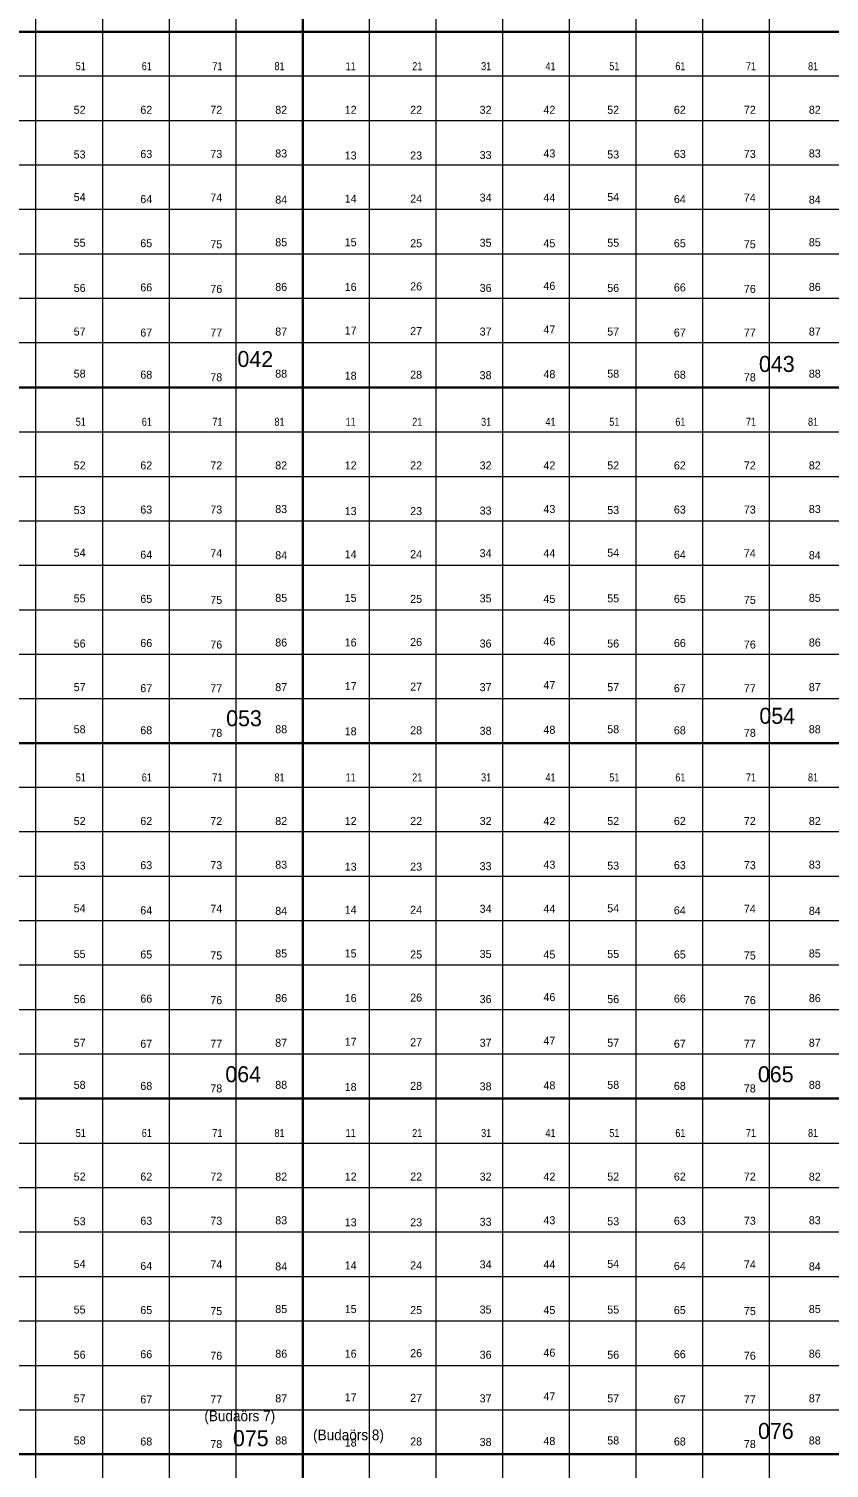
# Model space of a CAD drawing. Extents: x 639000 to 672000, y 222000 to 252000.
# Drawn here: x 643460 to 647960, y 233921 to 242017 of the extents above; entities that cross this region are included whole.
import ezdxf
from ezdxf.enums import TextEntityAlignment as Align

# ---------------------------------------------------------------- set-up
doc = ezdxf.new("R2010")
doc.units = 0
doc.header["$LTSCALE"] = 18
doc.layers.add('1', color=7, linetype='Continuous', lineweight=13)
doc.layers.add('2', color=7, linetype='Continuous')
doc.layers.add('29', color=7, linetype='Continuous')

msp = doc.modelspace()

# ---------------------------------------------------------------- linework, layer by layer
at = {"layer": '1', "lineweight": 35}
for p, q in [((645000, 224000), (645000, 250000)), ((639000, 242000), (672000, 242000)), ((672000, 240000), (639000, 240000)), ((639000, 238000), (672000, 238000)), ((672000, 236000), (639000, 236000)), ((639000, 234000), (672000, 234000))]:
    msp.add_line(p, q, dxfattribs=at)
at = {"layer": '1'}
for p, q in [((645375, 224000), (645375, 250000)), ((645750, 224000), (645750, 250000)), ((646125, 224000), (646125, 250000)), ((646500, 224000), (646500, 250000)), ((646875, 224000), (646875, 250000)), ((647250, 224000), (647250, 250000)), ((647625, 224000), (647625, 250000)), ((643500, 224000), (643500, 248000)), ((643875, 224000), (643875, 248000)), ((644250, 224000), (644250, 248000)), ((644625, 224000), (644625, 248000)), ((672000, 241750), (639000, 241750)), ((672000, 241500), (639000, 241500)), ((672000, 241250), (639000, 241250)), ((672000, 241000), (639000, 241000)), ((672000, 240750), (639000, 240750)), ((672000, 240500), (639000, 240500)), ((672000, 240250), (639000, 240250)), ((639000, 239750), (672000, 239750)), ((639000, 239500), (672000, 239500)), ((639000, 239250), (672000, 239250)), ((639000, 239000), (672000, 239000)), ((639000, 238750), (672000, 238750)), ((639000, 238500), (672000, 238500)), ((639000, 238250), (672000, 238250)), ((672000, 237750), (639000, 237750)), ((672000, 237500), (639000, 237500)), ((672000, 237250), (639000, 237250)), ((672000, 237000), (639000, 237000)), ((672000, 236750), (639000, 236750)), ((672000, 236500), (639000, 236500)), ((672000, 236250), (639000, 236250)), ((639000, 235750), (672000, 235750)), ((639000, 235500), (672000, 235500)), ((639000, 235250), (672000, 235250)), ((639000, 235000), (672000, 235000)), ((639000, 234750), (672000, 234750)), ((639000, 234500), (672000, 234500)), ((639000, 234250), (672000, 234250))]:
    msp.add_line(p, q, dxfattribs=at)

# ---------------------------------------------------------------- texts
at = {"layer": '2'}
for s, rotation, p in [('042', 359.64, (644732.8, 240114.64)), ('054', 359.64, (647667.4, 238108.18)), ('064', 359.94, (644664.8, 236092.18)), ('065', 359.94, (647659.41, 236092.18)), ('075', 359.94, (644707.66, 234045.25)), ('076', 359.94, (647660.08, 234085.86))]:
    msp.add_text(s, height=90, rotation=rotation, dxfattribs=at).set_placement(p, align=Align.CENTER)
for s, p in [('043', (647665.32, 240086.99)), ('053', (644669.58, 238094.38))]:
    msp.add_text(s, height=90, dxfattribs=at).set_placement(p, align=Align.CENTER)
at = {"layer": '2', "width": 0.95}
for s, p in [('(Budaörs 7)', (644645.65, 234185.85)), ('(Budaörs 8)', (645257.14, 234078.96))]:
    msp.add_text(s, height=60, dxfattribs=at).set_placement(p, align=Align.CENTER)
at = {"layer": '29', "width": 0.85}
for s, p in [('51', (643751.8, 241784.35)), ('61', (644123.23, 241784.35)), ('71', (644520.05, 241784.35)), ('81', (644869.26, 241784.35)), ('11', (645269.26, 241784.35)), ('21', (645643.86, 241784.35)), ('31', (646031.16, 241784.35)), ('41', (646393.07, 241784.35)), ('51', (646751.8, 241784.35)), ('61', (647123.23, 241784.35)), ('71', (647520.05, 241784.35)), ('81', (647869.26, 241784.35)), ('51', (643751.8, 239784.35)), ('61', (644123.23, 239784.35)), ('71', (644520.05, 239784.35)), ('81', (644869.26, 239784.35)), ('11', (645269.26, 239784.35)), ('21', (645643.86, 239784.35)), ('31', (646031.16, 239784.35)), ('41', (646393.07, 239784.35)), ('51', (646751.8, 239784.35)), ('61', (647123.23, 239784.35)), ('71', (647520.05, 239784.35)), ('81', (647869.26, 239784.35)), ('51', (643751.8, 237784.35)), ('61', (644123.23, 237784.35)), ('71', (644520.05, 237784.35)), ('81', (644869.26, 237784.35)), ('11', (645269.26, 237784.35)), ('21', (645643.86, 237784.35)), ('31', (646031.16, 237784.35)), ('41', (646393.07, 237784.35)), ('51', (646751.8, 237784.35)), ('61', (647123.23, 237784.35)), ('71', (647520.05, 237784.35)), ('81', (647869.26, 237784.35)), ('51', (643751.8, 235784.35)), ('61', (644123.23, 235784.35)), ('71', (644520.05, 235784.35)), ('81', (644869.26, 235784.35)), ('11', (645269.26, 235784.35)), ('21', (645643.86, 235784.35)), ('31', (646031.16, 235784.35)), ('41', (646393.07, 235784.35)), ('51', (646751.8, 235784.35)), ('61', (647123.23, 235784.35)), ('71', (647520.05, 235784.35)), ('81', (647869.26, 235784.35))]:
    msp.add_text(s, height=45, dxfattribs=at).set_placement(p, align=Align.CENTER)
at = {"layer": '29'}
for s, p in [('52', (643745.45, 241538.96)), ('62', (644120.05, 241538.96)), ('72', (644513.7, 241538.96)), ('82', (644878.78, 241538.96)), ('12', (645269.25, 241538.96)), ('22', (645637.51, 241538.96)), ('32', (646027.99, 241538.96)), ('42', (646386.72, 241538.96)), ('52', (646745.45, 241538.96)), ('62', (647120.05, 241538.96)), ('72', (647513.7, 241538.96)), ('82', (647878.78, 241538.96)), ('53', (643745.45, 241287.8)), ('63', (644120.05, 241290.68)), ('73', (644513.7, 241290.68)), ('83', (644878.78, 241293.57)), ('43', (646386.72, 241293.57)), ('53', (646745.45, 241287.8)), ('63', (647120.05, 241290.68)), ('73', (647513.7, 241290.68)), ('83', (647878.78, 241293.57)), ('13', (645269.26, 241282.02)), ('23', (645637.51, 241282.02)), ('33', (646027.99, 241284.91)), ('54', (643745.45, 241048.18)), ('74', (644513.7, 241045.29)), ('34', (646027.99, 241045.29)), ('44', (646386.72, 241045.29)), ('54', (646745.45, 241048.18)), ('74', (647513.7, 241045.29)), ('64', (644120.05, 241036.63)), ('84', (644878.78, 241033.74)), ('14', (645269.26, 241039.52)), ('24', (645637.51, 241039.52)), ('64', (647120.05, 241036.63)), ('84', (647878.78, 241033.74)), ('55', (643745.45, 240791.24)), ('65', (644120.05, 240788.36)), ('75', (644513.7, 240782.58)), ('85', (644878.78, 240794.13)), ('15', (645269.26, 240794.13)), ('25', (645637.51, 240788.35)), ('35', (646027.99, 240791.24)), ('45', (646386.72, 240788.35)), ('55', (646745.45, 240791.24)), ('65', (647120.05, 240788.36)), ('75', (647513.7, 240782.58)), ('85', (647878.78, 240794.13)), ('56', (643745.45, 240537.19)), ('66', (644120.05, 240540.08)), ('76', (644513.7, 240531.42)), ('86', (644878.78, 240542.96)), ('16', (645269.26, 240542.96)), ('26', (645637.51, 240545.85)), ('36', (646027.99, 240537.19)), ('46', (646386.72, 240548.74)), ('56', (646745.45, 240537.19)), ('66', (647120.05, 240540.08)), ('76', (647513.7, 240531.42)), ('86', (647878.78, 240542.96)), ('57', (643745.45, 240291.8)), ('67', (644120.05, 240286.03)), ('77', (644513.7, 240286.03)), ('87', (644878.78, 240291.8)), ('17', (645269.26, 240297.57)), ('27', (645637.51, 240294.69)), ('37', (646027.99, 240291.8)), ('47', (646386.72, 240303.35)), ('57', (646745.45, 240291.8)), ('67', (647120.05, 240286.03)), ('77', (647513.7, 240286.03)), ('87', (647878.78, 240291.8)), ('58', (643745.45, 240055.07)), ('68', (644120.05, 240049.3)), ('78', (644513.7, 240034.86)), ('88', (644878.78, 240055.07)), ('18', (645269.25, 240043.52)), ('28', (645637.51, 240049.3)), ('38', (646027.99, 240046.41)), ('48', (646386.72, 240052.18)), ('58', (646745.45, 240055.07)), ('68', (647120.05, 240049.3)), ('78', (647513.7, 240034.86)), ('88', (647878.78, 240055.07)), ('52', (643745.45, 239538.96)), ('62', (644120.05, 239538.96)), ('72', (644513.7, 239538.96)), ('82', (644878.78, 239538.96)), ('12', (645269.25, 239538.96)), ('22', (645637.51, 239538.96)), ('32', (646027.99, 239538.96)), ('42', (646386.72, 239538.96)), ('52', (646745.45, 239538.96)), ('62', (647120.05, 239538.96)), ('72', (647513.7, 239538.96)), ('82', (647878.78, 239538.96)), ('53', (643745.45, 239287.8)), ('63', (644120.05, 239290.68)), ('73', (644513.7, 239290.68)), ('83', (644878.78, 239293.57)), ('13', (645269.26, 239282.02)), ('23', (645637.51, 239282.02)), ('33', (646027.99, 239284.91)), ('43', (646386.72, 239293.57)), ('53', (646745.45, 239287.8)), ('63', (647120.05, 239290.68)), ('73', (647513.7, 239290.68)), ('83', (647878.78, 239293.57)), ('54', (643745.45, 239048.18)), ('64', (644120.05, 239036.63)), ('74', (644513.7, 239045.29)), ('84', (644878.78, 239033.74)), ('14', (645269.26, 239039.52)), ('24', (645637.51, 239039.52)), ('34', (646027.99, 239045.29)), ('44', (646386.72, 239045.29)), ('54', (646745.45, 239048.18)), ('64', (647120.05, 239036.63)), ('74', (647513.7, 239045.29)), ('84', (647878.78, 239033.74)), ('55', (643745.45, 238791.24)), ('65', (644120.05, 238788.36)), ('75', (644513.7, 238782.58)), ('85', (644878.78, 238794.13)), ('15', (645269.26, 238794.13)), ('25', (645637.51, 238788.35)), ('35', (646027.99, 238791.24)), ('45', (646386.72, 238788.35)), ('55', (646745.45, 238791.24)), ('65', (647120.05, 238788.36)), ('75', (647513.7, 238782.58)), ('85', (647878.78, 238794.13)), ('56', (643745.45, 238537.19)), ('66', (644120.05, 238540.08)), ('86', (644878.78, 238542.96)), ('16', (645269.26, 238542.96)), ('26', (645637.51, 238545.85)), ('36', (646027.99, 238537.19)), ('46', (646386.72, 238548.74)), ('56', (646745.45, 238537.19)), ('66', (647120.05, 238540.08)), ('86', (647878.78, 238542.96)), ('76', (644513.7, 238531.42)), ('76', (647513.7, 238531.42)), ('57', (643745.45, 238291.8)), ('87', (644878.78, 238291.8)), ('17', (645269.26, 238297.57)), ('27', (645637.51, 238294.69)), ('37', (646027.99, 238291.8)), ('47', (646386.72, 238303.35)), ('57', (646745.45, 238291.8)), ('87', (647878.78, 238291.8)), ('67', (644120.05, 238286.03)), ('77', (644513.7, 238286.03)), ('67', (647120.05, 238286.03)), ('77', (647513.7, 238286.03)), ('58', (643745.45, 238055.07)), ('68', (644120.05, 238049.3)), ('88', (644878.78, 238055.07)), ('28', (645637.51, 238049.3)), ('48', (646386.72, 238052.18)), ('58', (646745.45, 238055.07)), ('68', (647120.05, 238049.3)), ('88', (647878.78, 238055.07)), ('78', (644513.7, 238034.86)), ('18', (645269.25, 238043.52)), ('38', (646027.99, 238046.41)), ('78', (647513.7, 238034.86)), ('52', (643745.45, 237538.96)), ('62', (644120.05, 237538.96)), ('72', (644513.7, 237538.96)), ('82', (644878.78, 237538.96)), ('12', (645269.25, 237538.96)), ('22', (645637.51, 237538.96)), ('32', (646027.99, 237538.96)), ('42', (646386.72, 237538.96)), ('52', (646745.45, 237538.96)), ('62', (647120.05, 237538.96)), ('72', (647513.7, 237538.96)), ('82', (647878.78, 237538.96)), ('53', (643745.45, 237287.8)), ('63', (644120.05, 237290.68)), ('73', (644513.7, 237290.68)), ('83', (644878.78, 237293.57)), ('13', (645269.26, 237282.02)), ('23', (645637.51, 237282.02)), ('33', (646027.99, 237284.91)), ('43', (646386.72, 237293.57)), ('53', (646745.45, 237287.8)), ('63', (647120.05, 237290.68)), ('73', (647513.7, 237290.68)), ('83', (647878.78, 237293.57)), ('54', (643745.45, 237048.18)), ('64', (644120.05, 237036.63)), ('74', (644513.7, 237045.29)), ('84', (644878.78, 237033.74)), ('14', (645269.26, 237039.52)), ('24', (645637.51, 237039.52)), ('34', (646027.99, 237045.29)), ('44', (646386.72, 237045.29)), ('54', (646745.45, 237048.18)), ('64', (647120.05, 237036.63)), ('74', (647513.7, 237045.29)), ('84', (647878.78, 237033.74)), ('55', (643745.45, 236791.24)), ('65', (644120.05, 236788.36)), ('75', (644513.7, 236782.58)), ('85', (644878.78, 236794.13)), ('15', (645269.26, 236794.13)), ('25', (645637.51, 236788.35)), ('35', (646027.99, 236791.24)), ('45', (646386.72, 236788.35)), ('55', (646745.45, 236791.24)), ('65', (647120.05, 236788.36)), ('75', (647513.7, 236782.58)), ('85', (647878.78, 236794.13)), ('56', (643745.45, 236537.19)), ('66', (644120.05, 236540.08)), ('76', (644513.7, 236531.42)), ('86', (644878.78, 236542.96)), ('16', (645269.26, 236542.96)), ('26', (645637.51, 236545.85)), ('36', (646027.99, 236537.19)), ('46', (646386.72, 236548.74)), ('56', (646745.45, 236537.19)), ('66', (647120.05, 236540.08)), ('76', (647513.7, 236531.42)), ('86', (647878.78, 236542.96)), ('57', (643745.45, 236291.8)), ('67', (644120.05, 236286.03)), ('77', (644513.7, 236286.03)), ('87', (644878.78, 236291.8)), ('17', (645269.26, 236297.57)), ('27', (645637.51, 236294.69)), ('37', (646027.99, 236291.8)), ('47', (646386.72, 236303.35)), ('57', (646745.45, 236291.8)), ('67', (647120.05, 236286.03)), ('77', (647513.7, 236286.03)), ('87', (647878.78, 236291.8)), ('58', (643745.45, 236055.07)), ('68', (644120.05, 236049.3)), ('78', (644513.7, 236034.86)), ('88', (644878.78, 236055.07)), ('18', (645269.25, 236043.52)), ('28', (645637.51, 236049.3)), ('38', (646027.99, 236046.41)), ('48', (646386.72, 236052.18)), ('58', (646745.45, 236055.07)), ('68', (647120.05, 236049.3)), ('78', (647513.7, 236034.86)), ('88', (647878.78, 236055.07)), ('52', (643745.45, 235538.96)), ('62', (644120.05, 235538.96)), ('72', (644513.7, 235538.96)), ('82', (644878.78, 235538.96)), ('12', (645269.25, 235538.96)), ('22', (645637.51, 235538.96)), ('32', (646027.99, 235538.96)), ('42', (646386.72, 235538.96)), ('52', (646745.45, 235538.96)), ('62', (647120.05, 235538.96)), ('72', (647513.7, 235538.96)), ('82', (647878.78, 235538.96)), ('53', (643745.45, 235287.8)), ('63', (644120.05, 235290.68)), ('73', (644513.7, 235290.68)), ('83', (644878.78, 235293.57)), ('13', (645269.26, 235282.02)), ('23', (645637.51, 235282.02)), ('33', (646027.99, 235284.91)), ('43', (646386.72, 235293.57)), ('53', (646745.45, 235287.8)), ('63', (647120.05, 235290.68)), ('73', (647513.7, 235290.68)), ('83', (647878.78, 235293.57)), ('54', (643745.45, 235048.18)), ('64', (644120.05, 235036.63)), ('74', (644513.7, 235045.29)), ('84', (644878.78, 235033.74)), ('14', (645269.26, 235039.52)), ('24', (645637.51, 235039.52)), ('34', (646027.99, 235045.29)), ('44', (646386.72, 235045.29)), ('54', (646745.45, 235048.18)), ('64', (647120.05, 235036.63)), ('74', (647513.7, 235045.29)), ('84', (647878.78, 235033.74)), ('55', (643745.45, 234791.24)), ('65', (644120.05, 234788.36)), ('75', (644513.7, 234782.58)), ('85', (644878.78, 234794.13)), ('15', (645269.26, 234794.13)), ('25', (645637.51, 234788.35)), ('35', (646027.99, 234791.24)), ('45', (646386.72, 234788.35)), ('55', (646745.45, 234791.24)), ('65', (647120.05, 234788.36)), ('75', (647513.7, 234782.58)), ('85', (647878.78, 234794.13)), ('56', (643745.45, 234537.19)), ('66', (644120.05, 234540.08)), ('76', (644513.7, 234531.42)), ('86', (644878.78, 234542.96)), ('16', (645269.26, 234542.96)), ('26', (645637.51, 234545.85)), ('36', (646027.99, 234537.19)), ('46', (646386.72, 234548.74)), ('56', (646745.45, 234537.19)), ('66', (647120.05, 234540.08)), ('76', (647513.7, 234531.42)), ('86', (647878.78, 234542.96)), ('57', (643745.45, 234291.8)), ('67', (644120.05, 234286.03)), ('77', (644513.7, 234286.03)), ('87', (644878.78, 234291.8)), ('17', (645269.26, 234297.57)), ('27', (645637.51, 234294.69)), ('37', (646027.99, 234291.8)), ('47', (646386.72, 234303.35)), ('57', (646745.45, 234291.8)), ('67', (647120.05, 234286.03)), ('77', (647513.7, 234286.03)), ('87', (647878.78, 234291.8)), ('58', (643745.45, 234055.07)), ('68', (644120.05, 234049.3)), ('78', (644513.7, 234034.86)), ('88', (644878.78, 234055.07)), ('18', (645269.25, 234043.52)), ('28', (645637.51, 234049.3)), ('38', (646027.99, 234046.41)), ('48', (646386.72, 234052.18)), ('58', (646745.45, 234055.07)), ('68', (647120.05, 234049.3)), ('78', (647513.7, 234034.86)), ('88', (647878.78, 234055.07))]:
    msp.add_text(s, height=45, dxfattribs=at).set_placement(p, align=Align.CENTER)

doc.saveas('drawing.dxf')
